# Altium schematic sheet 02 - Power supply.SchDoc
size B; CompanyName: Microchip Technology Inc.; Organization: Microchip Technology; Address1: 2355 West Chandler Blvd.; Address2: Chandler, AZ  85224; Address4: USA; DocumentNumber: 2; SheetNumber: 2; SheetTotal: 13; SheetTitle: Power supply
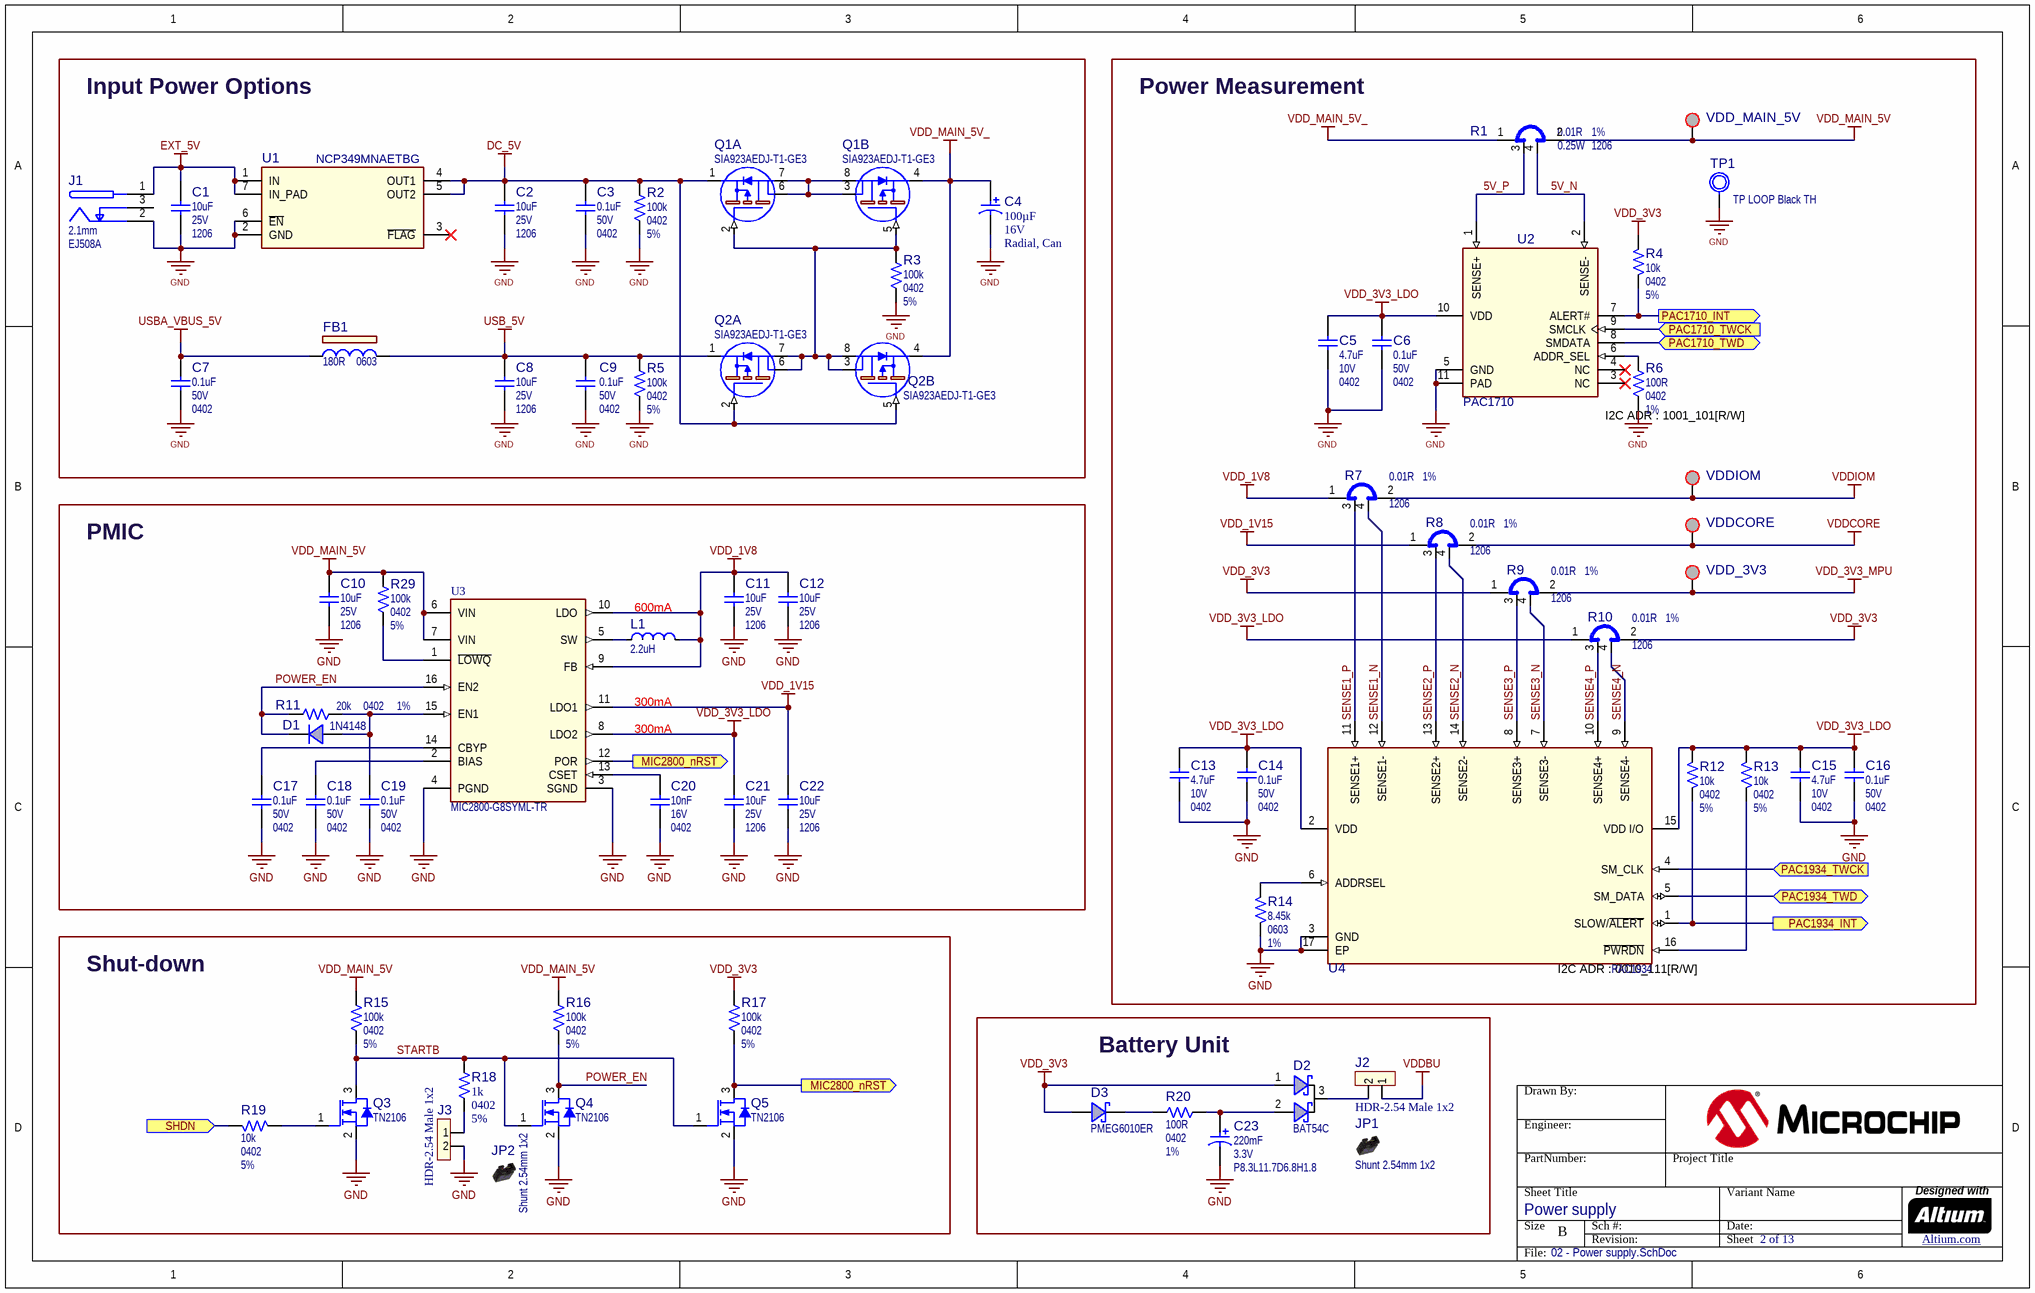
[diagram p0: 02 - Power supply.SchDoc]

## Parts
?  (no value)  (graphical)
C1  value 10uF  Voltage: 25V  Package: 1206  [CAP_C_1206]  (hidden comment: Capacitor NP)
C2  value 10uF  Voltage: 25V  Package: 1206  [CAP_C_1206]  (hidden comment: Capacitor NP)
C3  value 0.1uF  Voltage: 50V  Package: 0402  [CAP_C_0402]  (hidden comment: Capacitor NP)
C4  value 100µF  Voltage: 16V  Package: Radial, Can  [CAP_RAD_P2D5H12.5]  (hidden comment: Capacitor POL)
C5  value 4.7uF  Voltage: 10V  Package: 0402  [CAP_C_0402]  (hidden comment: Capacitor NP)
C6  value 0.1uF  Voltage: 50V  Package: 0402  [CAP_C_0402]  (hidden comment: Capacitor NP)
C7  value 0.1uF  Voltage: 50V  Package: 0402  [CAP_C_0402]  (hidden comment: Capacitor NP)
C8  value 10uF  Voltage: 25V  Package: 1206  [CAP_C_1206]  (hidden comment: Capacitor NP)
C9  value 0.1uF  Voltage: 50V  Package: 0402  [CAP_C_0402]  (hidden comment: Capacitor NP)
C10  value 10uF  Voltage: 25V  Package: 1206  [CAP_C_1206]  (hidden comment: Capacitor NP)
C11  value 10uF  Voltage: 25V  Package: 1206  [CAP_C_1206]  (hidden comment: Capacitor NP)
C12  value 10uF  Voltage: 25V  Package: 1206  [CAP_C_1206]  (hidden comment: Capacitor NP)
C13  value 4.7uF  Voltage: 10V  Package: 0402  [CAP_C_0402]  (hidden comment: Capacitor NP)
C14  value 0.1uF  Voltage: 50V  Package: 0402  [CAP_C_0402]  (hidden comment: Capacitor NP)
C15  value 4.7uF  Voltage: 10V  Package: 0402  [CAP_C_0402]  (hidden comment: Capacitor NP)
C16  value 0.1uF  Voltage: 50V  Package: 0402  [CAP_C_0402]  (hidden comment: Capacitor NP)
C17  value 0.1uF  Voltage: 50V  Package: 0402  [CAP_C_0402]  (hidden comment: Capacitor NP)
C18  value 0.1uF  Voltage: 50V  Package: 0402  [CAP_C_0402]  (hidden comment: Capacitor NP)
C19  value 0.1uF  Voltage: 50V  Package: 0402  [CAP_C_0402]  (hidden comment: Capacitor NP)
C20  value 10nF  Voltage: 16V  Package: 0402  [CAP_C_0402]  (hidden comment: Capacitor NP)
C21  value 10uF  Voltage: 25V  Package: 1206  [CAP_C_1206]  (hidden comment: Capacitor NP)
C22  value 10uF  Voltage: 25V  Package: 1206  [CAP_C_1206]  (hidden comment: Capacitor NP)
C23  value 220mF  Voltage: 3.3V  Package: P8.3L11.7D6.8H1.8  [CAP_AX_P8.3L11.7D6.8H1.8]  (hidden comment: Capacitor POL)
D1  value 1N4148  [SOD-323]  (hidden comment: Diode Single)
D2  value BAT54C  [SOT-23-3]  (hidden comment: Diode Schottky Dual CK)
D3  value PMEG6010ER  [SOD-123]  (hidden comment: Diode Schottky)
FB1  value 180R  Package: 0603  [IND_C_0603]  (hidden comment: Ferrite Bead)
J1  value 2.1mm  Manufacturer Part Number 1: EJ508A  [CON_JACK_POWER_TH_RA_MPD_EJ508A]  (hidden comment: CON JACK 2C 3P SPST)
J2  value HDR-2.54 Male 1x2  [HDR_M_2.54_1x2]  (hidden comment: Header 1x2)
J3  value HDR-2.54 Male 1x2  [HDR_M_2.54_1x2]  (hidden comment: Header 1x2)
JP1  value Shunt 2.54mm 1x2  [Jumper_Mechanical]  (hidden comment: Jumper Mechanical)  (mechanical)
JP2  value Shunt 2.54mm 1x2  [Jumper_Mechanical]  (hidden comment: Jumper Mechanical)  (mechanical)
L1  value 2.2uH  [IND_C_1008]  (hidden comment: Inductor)
Q1  SIA923AEDJ-T1-GE3  [SiA923AEDJ PPAK_SC70_6L]  (parts A,B of 2)
Q2  SIA923AEDJ-T1-GE3  [SiA923AEDJ PPAK_SC70_6L]  (parts A,B of 2)
Q3  value TN2106  [SOT-23-3]  (hidden comment: Transistor MOS-N GSD)
Q4  value TN2106  [SOT-23-3]  (hidden comment: Transistor MOS-N GSD)
Q5  value TN2106  [SOT-23-3]  (hidden comment: Transistor MOS-N GSD)
R1  value 0.01R  Package: 1206  Tolerance: 1%  Power: 0.25W  [RES_C_1206_SHUNT]  (hidden comment: Shunt 4 Pin)
R2  value 100k  Package: 0402  Tolerance: 5%  [RES_C_0402]  (hidden comment: Resistor)
R3  value 100k  Package: 0402  Tolerance: 5%  [RES_C_0402]  (hidden comment: Resistor)
R4  value 10k  Package: 0402  Tolerance: 5%  [RES_C_0402]  (hidden comment: Resistor)
R5  value 100k  Package: 0402  Tolerance: 5%  [RES_C_0402]  (hidden comment: Resistor)
R6  value 100R  Package: 0402  Tolerance: 1%  [RES_C_0402]  (hidden comment: Resistor)
R7  value 0.01R  Package: 1206  Tolerance: 1%  [RES_C_1206_SHUNT]  (hidden comment: Shunt 4 Pin)
R8  value 0.01R  Package: 1206  Tolerance: 1%  [RES_C_1206_SHUNT]  (hidden comment: Shunt 4 Pin)
R9  value 0.01R  Package: 1206  Tolerance: 1%  [RES_C_1206_SHUNT]  (hidden comment: Shunt 4 Pin)
R10  value 0.01R  Package: 1206  Tolerance: 1%  [RES_C_1206_SHUNT]  (hidden comment: Shunt 4 Pin)
R11  value 20k  Package: 0402  Tolerance: 1%  [RES_C_0402]  (hidden comment: Resistor)
R12  value 10k  Package: 0402  Tolerance: 5%  [RES_C_0402]  (hidden comment: Resistor)
R13  value 10k  Package: 0402  Tolerance: 5%  [RES_C_0402]  (hidden comment: Resistor)
R14  value 8.45k  Package: 0603  Tolerance: 1%  [RES_C_0603]  (hidden comment: Resistor)
R15  value 100k  Package: 0402  Tolerance: 5%  [RES_C_0402]  (hidden comment: Resistor)
R16  value 100k  Package: 0402  Tolerance: 5%  [RES_C_0402]  (hidden comment: Resistor)
R17  value 100k  Package: 0402  Tolerance: 5%  [RES_C_0402]  (hidden comment: Resistor)
R18  value 1k  Package: 0402  Tolerance: 5%  [RES_C_0402]  (hidden comment: Resistor)
R19  value 10k  Package: 0402  Tolerance: 5%  [RES_C_0402]  (hidden comment: Resistor)
R20  value 100R  Package: 0402  Tolerance: 1%  [RES_C_0402]  (hidden comment: Resistor)
R29  value 100k  Package: 0402  Tolerance: 5%  [RES_C_0402]  (hidden comment: Resistor)
TP1  value TP LOOP Black TH  [CON_TP_TH_V_BLK_KEC_5011]  (hidden comment: GND)
U1  value NCP349MNAETBG  [DFN-6_2x1.6_EP0.4x0.35]  (hidden comment: NCP349 DFN-6)
U2  value PAC1710  [DFN-10_3x3]  (hidden comment: PAC1710 DFN-10)
U3  value MIC2800-G8SYML-TR  [QFN-16_3X3]  (hidden comment: MIC2800 VFQFN-16)
U4  value PAC1934  [UQFN-16_4X4_EP2.6X2.6]  (hidden comment: PAC1934 UQFN-16)
VDD_3V3  SMD Test Point  [TP_1x1_SMD]  (value not drawn)  (no BOM)
VDD_MAIN_5V  SMD Test Point  [TP_1x1_SMD]  (value not drawn)  (no BOM)
VDDCORE  SMD Test Point  [TP_1x1_SMD]  (value not drawn)  (no BOM)
VDDIOM  SMD Test Point  [TP_1x1_SMD]  (value not drawn)  (no BOM)

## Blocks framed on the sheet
Input Power Options: C1-C4 C7-C9 FB1 J1 Q1 Q2 R2 R3 R5 U1
Power Measurement: C5 C6 C13-C16 R1 R4 R6-R10 R12-R14 TP1 U2 U4 VDD_3V3 VDD_MAIN_5V VDDCORE VDDIOM
PMIC: C10-C12 C17-C22 D1 L1 R11 R29 U3
Shut-down: J3 JP2 Q3-Q5 R15-R19
Battery Unit: C23 D2 D3 J2 JP1 R20

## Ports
MIC2800_nRST (out), PAC1710_INT (out), PAC1710_TWCK (in), PAC1710_TWD (bidir), PAC1934_INT (out), PAC1934_TWCK (in), PAC1934_TWD (bidir), SHDN (in)

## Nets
DC_5V: C2.1 C3.1 Q1.1(S1) Q2.2(G1) Q2.5(G2) R2.2 U1.4(OUT1) U1.5(OUT2)
EXT_5V: C1.1 J1.1(PLUS) U1.1(IN) U1.7(IN_PAD)
GND: C1.2 C2.2 C3.2 C4.2 C5.1 C6.1 C7.2 C8.2 C9.2 C10.2 C11.2 C12.2 C13.1 C14.1 C15.1 C16.1 C17.2 C18.2 C19.2 C20.2 C21.2 C22.2 C23.2 J1.2(COM) J3.2 Q3.2(S) Q4.2(S) Q5.2(S) R2.1 R3.1 R5.1 R6.2 R14.1 TP1.1 U1.2(GND) U1.6(~{EN}) U2.5(GND) U2.11(PAD) U3.3(SGND) U3.4(PGND) U4.3(GND) U4.17(EP)
USB_5V: C8.1 C9.1 FB1.2 Q2.1(S1) R5.2
USBA_VBUS_5V: C7.1 FB1.1
VDD_1V8: C11.1 C12.1 L1.2(F) R7.1 U3.9(FB) U3.10(LDO)
VDD_1V15: C22.1 R8.1 U3.11(LDO1)
VDD_3V3: D2.1(A) D3.1(A) R4.2 R9.1 R10.2 R17.2
VDD_3V3_LDO: C5.2 C6.2 C13.2 C14.2 C15.2 C16.2 C21.1 R10.1 R12.2 R13.2 U2.10(VDD) U3.8(LDO2) U4.2(VDD) U4.15(VDD_I/O)
VDD_3V3_MPU: R9.2 VDD_3V3.1
VDD_MAIN_5V: C10.1 R1.2 R15.2 R16.2 R29.2 U3.6(VIN) U3.7(VIN) VDD_MAIN_5V.1
VDD_MAIN_5V_: C4.1 Q1.4(S2) Q2.4(S2) R1.1
VDDBU: J2.1
VDDCORE: R8.2 VDDCORE.1
VDDIOM: R7.2 VDDIOM.1
5V_N: R1.4 U2.2(SENSE-)
5V_P: R1.3 U2.1(SENSE+)
MIC2800_nRST: Q5.3(D) R17.1 U3.12(POR) ; port MIC2800_nRST
PAC1710_INT: R4.1 U2.7(ALERT#) ; port PAC1710_INT
PAC1710_TWCK: U2.9(SMCLK) ; port PAC1710_TWCK
PAC1710_TWD: U2.8(SMDATA) ; port PAC1710_TWD
PAC1934_INT: R12.1 U4.1(SLOW/~{ALERT}) ; port PAC1934_INT
PAC1934_TWCK: U4.4(SM_CLK) ; port PAC1934_TWCK
PAC1934_TWD: U4.5(SM_DATA) ; port PAC1934_TWD
POWER_EN: D1.2(K) Q4.3(D) R11.1 R16.1 U3.16(EN2)
SENSE1_N: R7.4 U4.12(SENSE1-)
SENSE1_P: R7.3 U4.11(SENSE1+)
SENSE2_N: R8.4 U4.14(SENSE2-)
SENSE2_P: R8.3 U4.13(SENSE2+)
SENSE3_N: R9.4 U4.7(SENSE3-)
SENSE3_P: R9.3 U4.8(SENSE3+)
SENSE4_N: R10.4 U4.9(SENSE4-)
SENSE4_P: R10.3 U4.10(SENSE4+)
SHDN: R19.2 ; port SHDN
STARTB: Q3.3(D) Q4.1(G) Q5.1(G) R15.1 R18.2
NetC17_1: C17.1 U3.14(CBYP)
NetC18_1: C18.1 U3.2(BIAS)
NetC19_1: C19.1 D1.1(A) R11.2 U3.15(EN1)
NetC20_1: C20.1 U3.13(CSET)
NetC23_1: C23.1 D2.2(A) R20.2
NetD2_3: D2.3(KK) J2.2
NetD3_2: D3.2(K) R20.1
NetJ3_1: J3.1 R18.1
NetL1_1: L1.1(S) U3.5(SW)
NetQ1_2: Q1.2(G1) Q1.5(G2) Q2.3(D2) Q2.6(D1) Q2.7(D1_2) Q2.8(D2_2) R3.2
NetQ1_3: Q1.3(D2) Q1.6(D1) Q1.7(D1_2) Q1.8(D2_2)
NetQ3_1: Q3.1(G) R19.1
NetR6_1: R6.1 U2.6(ADDR_SEL)
NetR13_1: R13.1 U4.16(~{PWRDN})
NetR14_2: R14.2 U4.6(ADDRSEL)
NetR29_1: R29.1 U3.1(~{LOWQ})

Not connected (* = marked no-connect by the designer): J1 3(SWITCH); U1 3(~{FLAG})*; U2 3(NC)* 4(NC)*

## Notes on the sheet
- I2C ADR : 1001_101[R/W]
- (near L1) 600mA
- 300mA
- (near U4) I2C ADR : 0010_111[R/W]

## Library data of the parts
? = Title Block B
C1 C2 C8 C10-C12 C21 C22 = CAP1418: Capacitor; Manufacturer 1: Samsung Electro-Mechanics America, Inc; Manufacturer Part Number 1: CL31B106KAHNFNE; Description_: CAP CER 10uF 25V 10% X7R SMD 1206; Dev Tools Status: Design; Tolerance: 10%; Temperature Coeffcient: X7R; Type: Ceramic; Populated: YES; Owner: Sorin Stanoaia
C3 C6 C7 C9 C14 C16-C19 = CAP1463: Capacitor; Manufacturer 1: TDK Corporation; Manufacturer Part Number 1: C1005X7R1H104K050BB; Description_: CAP CER 0.1uF 50V 10% X7R SMD 0402; Dev Tools Status: Production; Tolerance: 10%; Temperature Coeffcient: X7R; Type: Ceramic; Owner: Jamus Griego; Populated: YES
C4 = CAP1834: Capacitor; Manufacturer 1: Wurth Electronics Inc.; Manufacturer Part Number 1: 860010372006; Description_: CAP 100 UF 20% 16 V; Dev Tools Status: Design; Tolerance: ±20%; Type: Aluminum; Owner: Ed Kennedy; Populated: YES
C5 C13 C15 = CAP1684: Capacitor; Manufacturer 1: TDK Corporation; Manufacturer Part Number 1: C1005X5R1A475K050BC; Description_: CAP CER 4.7uF 10V 10% X5R SMD 0402; Dev Tools Status: Production; Tolerance: 10%; Temperature Coeffcient: X5R; Type: Ceramic; Owner: Jesus Aviles; Populated: YES
C20 = CAP0278: Capacitor; Manufacturer 1: KEMET; Manufacturer Part Number 1: C0402C103K4RACTU; Description_: CAP CER 10000pF 16V 10% X7R SMD 0402; Dev Tools Status: Production; Tolerance: 10%; Temperature Coeffcient: X7R; Type: Ceramic; Populated: YES
C23 = CAP1762: Capacitor; Manufacturer 1: Elna America; Manufacturer Part Number 1: DSK-3R3H204T614-H2L; Description_: CAP SUPERCAP 200mF 3.3V -20% +80% 200Ohm AX P8.3L11.7D6.8H1.8; Dev Tools Status: Production; Tolerance: -20%, +80%; ESR: 200R; Type: Supercap; Owner: Alexandru Chiser - M19201; Populated: YES
D1 = DIODE0096: Manufacturer 1: Diodes Incorporated; Manufacturer Part Number 1: 1N4148WS-7-F; Description_: DIO RECT 1N4148WS 1.25V 150mA 75V SOD-323; Dev Tools Status: Production; Type: Rectifier Single; Forward Current: 150mA; Power: 200mW; Reverse Current: 50uA; Reverse Voltage: 75V; Populated: YES
D2 = DIODE0056: Manufacturer 1: Diodes Incorporated; Manufacturer Part Number 1: BAT54CTA; Description_: DIO SCTKYARR BAT54C 530mV 200mA 30V SOT-23-3; Dev Tools Status: Production; Type: Schottky Array; Forward Current: 200mA; Power: 330mW; Reverse Current: 2.5uA; Reverse Voltage: 30V; Populated: Yes
D3 = DIODE1254: DIO SCTKY RB160M-60TR 550mV 1A 60V SMD SOD-123F; Manufacturer 1: NXP Semiconductors                                                                               NXP Semiconductors; Manufacturer Part Number 1: PMEG6010ER,115; Description_: DIODE SCTKY PMEG6010ER 530mV 1A 60V SMD SOD-123; Dev Tools Status: Design; Type: Schottky Single; Power: 0.95W; Reverse Current: 60uA; Reverse Recovery Time: 500ns; Owner: Sorin Stanoaia; Populated: YES
FB1 = IND1453: Manufacturer 1: Murata Electronics North America; Manufacturer Part Number 1: BLM18PG181SN1D; Description_: FERRITE 180R 1.5A SMD 0603; Dev Tools Status: Design; Owner: Dragos Danaila; DCR: 0.09R; Saturation Current: 1.5A; Test Frequency: 100MHz; Populated: YES
J1 = CON1560: Manufacturer 1: MPD (Memory Protection Devices); Description_: CON POWER 2.1mm 5.5mm Switch Slotted TH R/A; Dev Tools Status: Production; Owner: Mark Loper; Populated: YES
J2 J3 = CON1312: Manufacturer 1: Sullins Connector Solutions; Manufacturer Part Number 1: PREC002SAAN-RC; Description_: CON HDR-2.54 Male 1x2 Tin 5.84MH TH VERT; Dev Tools Status: Production; Owner: Randolph Sobrepena; Populated: YES
JP1 JP2 = HW1006: Manufacturer 1: 3M; Manufacturer Part Number 1: 969102-0000-DA; MCHP-ID: HW1006; Description_: MECH HW JUMPER 2.54mm 1x2; Dev Tools Status: Production; Owner: Mike Ragsdale; Populated: MECH
L1 = IND1348: Manufacturer 1: TDK; Manufacturer Part Number 1: MLP2520H2R2MT0S1; Description_: INDUCTOR 2.2uH 1.3A 20% SMD 1008; Dev Tools Status: Design; Owner: Razvan Cristescu; DCR: 0.117R; RMS Current: 1.3A; Test Frequency: 2MHz; Populated: YES
Q1 Q2 = TRA1245: Manufacturer 1: Vishay Siliconix; Description_: TRANS FET DUAL P+P SIA923AEDJ -20V -4.5A 7.8W SC70-6L; Dev Tools Status: Design; Type: FET; Current: -4.5A; Drain to Source Voltage: -20V; Gate to Source Voltage: 900mV; Power: 7.8W; Owner: Dragos Danaila; Populated: YES
Q3-Q5 = MIC7420: Transistor MOS; Manufacturer 1: Microchip Technology; Manufacturer Part Number 1: TN2106K1-G; Description_: MCHP ANALOG MOSFET N-CH TN2106 60V 280mA 360mW 2.5R SOT23-3; Type: MOSFET; Dev Tools Status: Production; Owner: Ilie Galan; Populated: YES
R1 = RSMT1231: Shunt; Manufacturer 1: Yageo; Manufacturer Part Number 1: PF1206FRF070R01L; Description_: RES SHUNT 0.01R 1% 1/4W 1206; Dev Tools Status: Design; Voltage: 50mV; Temperature Coeffcient: 100ppm/C; Current: 5A; Owner: Dragos Danaila; Populated: YES
R2 R3 R5 R15-R17 R29 = RES2196: Manufacturer 1: Yageo; Manufacturer Part Number 1: RC0402JR-07100KL; Description_: RES TKF 100k 5% 1/16W SMD 0402; Dev Tools Status: Design; Temperature Coeffcient: 100ppm/C; Power: 1/16W; Owner: Ilie Galan; Populated: YES
R4 R12 R13 R19 = RSMT0439: Manufacturer 1: Vishay; Manufacturer Part Number 1: CRCW040210K0JNED; Description_: RES TKF 10k 5% 1/16W SMD 0402; Dev Tools Status: Production; Voltage: 50V; Temperature Coeffcient: 100ppm/C; Power: 1/16W; Populated: Yes
R6 R20 = RES1587: Manufacturer 1: Yageo; Manufacturer Part Number 1: RC0402FR-07100RL; Description_: RES TKF 100R 1% 1/16W SMD 0402; Dev Tools Status: Design; Voltage: 50V; Temperature Coeffcient: 100ppm/C; Power: 1/16W; Owner: Sorin Stanoaia; Populated: YES
R7-R10 = RSMT1231: Shunt; Manufacturer 1: Yageo; Manufacturer Part Number 1: PF1206FRF070R01L; Description_: RES SHUNT 0.01R 1% 1/4W 1206; Dev Tools Status: Design; Voltage: 50mV; Temperature Coeffcient: 100ppm/C; Current: 5A; Power: 1/4W; Owner: Dragos Danaila; Populated: YES
R11 = RSMT1238: Manufacturer 1: Yageo; Manufacturer Part Number 1: RC0402FR-0720KL; Description_: RES TKF 20K 1% 1/16W SMD 0402; Dev Tools Status: Design; Voltage: 100V; Temperature Coeffcient: 100ppm/C; Current: 1A; Power: 1/16; Owner: Dragos Danaila; Populated: YES
R14 = RSMT0440: Manufacturer 1: Yageo; Manufacturer Part Number 1: 9C06031A8451FKHFT; Description_: RES TKF 8.45k 1% 1/10W SMD 0603; Dev Tools Status: Production; Voltage: 50V; Temperature Coeffcient: 100ppm/C; Power: 1/10W; Populated: Yes
R18 = RSMT0316: Manufacturer 1: Panasonic; Manufacturer Part Number 1: ERJ-2GEJ102X; Description_: RES TKF 1k 5% 1/16W SMD 0402; Dev Tools Status: Production; Voltage: 50V; Temperature Coeffcient: 200ppm/C; Power: 1/16W; Owner: Tad Ahlvers; Populated: YES
TP1 = MISC0025: Test Point; Manufacturer 1: Keystone; Manufacturer Part Number 1: 5011; Description_: CON TP LOOP Black TH; Dev Tools Status: Production; Owner: Tad Ahlvers; Populated: YES
U1 = IC1481: Manufacturer 1: ON Semiconductor; MCHP-ID: IC1481; Description_: IC POWER NCP349MNAETBG Power Supply Controller Overvoltage Protection DFN-6; Dev Tools Status: Design; Vin: 1.2 V to 28 V; Owner: Ciprian Abramov; Populated: YES
U2 = MIC6142: Manufacturer 1: Microchip Technology; Manufacturer Part Number 1: PAC1710-1-AIA-TR; Description_: MCHP ANALOG CURRENT SENSE MONITOR PAC1710-1-AIA-TR DFN-10; Dev Tools Status: Production; Owner: Bogdan Popescu; Populated: YES
U3 = MIC7858: Manufacturer 1: Microchip Technology; Manufacturer Part Number 1: MIC2800-G8SYML; Description_: MCHP ANALOG SWITCHER Buck 1.8V to 3.3V MIC2800-G8SYML-TR VFQFN-16; Dev Tools Status: Design; Owner: Dragos Danaila; Populated: YES
U4 = MIC7010: Manufacturer 1: Microchip Technology; Manufacturer Part Number 1: PAC1934-I/JQ; Description_: MCHP ANALOG POWER CURRENT SENSE MONITOR PAC1934-I/JQ UQFN-16; Dev Tools Status: Production; Owner: Razvan Cristescu; Populated: YES
VDD_3V3 VDD_MAIN_5V VDDCORE VDDIOM = TEST-POINT: Test Point pad 1.00mm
